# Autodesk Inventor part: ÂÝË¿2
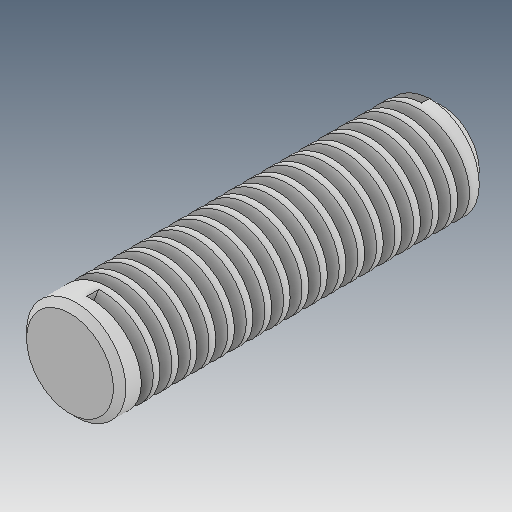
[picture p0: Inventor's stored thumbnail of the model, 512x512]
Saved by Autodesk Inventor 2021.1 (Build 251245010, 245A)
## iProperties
Created: 2019-04
Part Number: ÂÝË¿2
Material: Ogólny
Document SubType Name: Modeling
Designer: user
Density: 1 g/cm^3
Appearance: Domyślna
Author: user
Revision Number: ÈÎºÎ
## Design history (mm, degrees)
feature "ÊäÈë1"
node "Bryła1"
